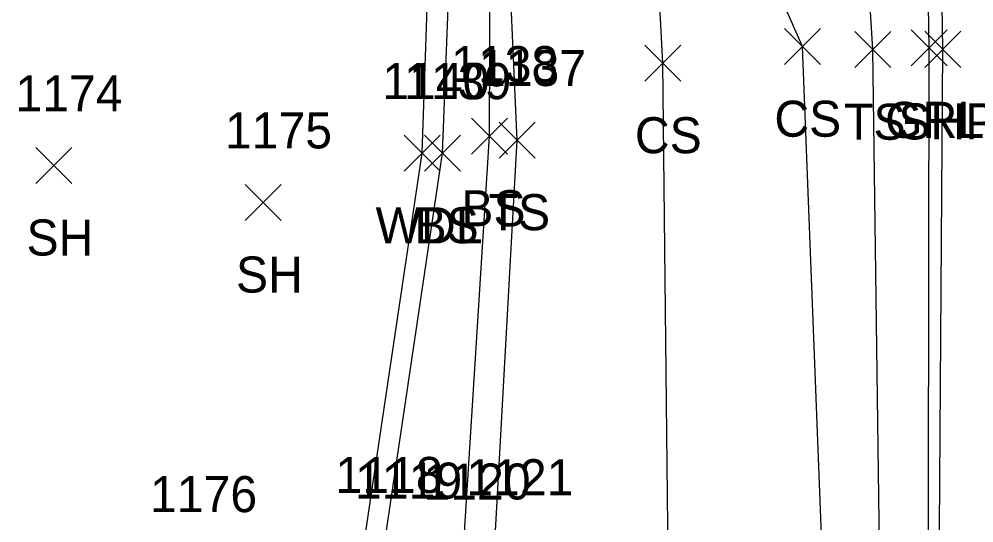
# Model space of a CAD drawing. Extents: x 1618262 to 1622220, y 273782 to 283685.
# Drawn here: x 1621993.1 to 1622046.2, y 282720.6 to 282748.6 of the extents above; entities that cross this region are included whole.
import ezdxf

# ---------------------------------------------------------------- set-up
doc = ezdxf.new("R2010")
doc.units = 0
for name, color, linetype in [('L_A', 7, 'Continuous'), ('L_I', 7, 'Continuous'), ('L_TIC', 7, 'Continuous'), ('LAWA', 7, 'Continuous'), ('LELB', 7, 'Continuous'), ('P_A', 7, 'Continuous'), ('P_TIC', 7, 'Continuous'), ('PSP', 7, 'Continuous'), ('R_A', 7, 'Continuous'), ('R_TIC', 7, 'Continuous'), ('RGR', 7, 'Continuous')]:
    doc.layers.add(name, color=color, linetype=linetype)

msp = doc.modelspace()

# ---------------------------------------------------------------- linework, layer by layer
at = {"layer": 'L_TIC'}
for points in [[(1622035.634, 282746.032), (1622037.634, 282748.032)], [(1622037.634, 282746.032), (1622035.634, 282748.032)], [(1622039.536, 282745.865), (1622041.536, 282747.865)], [(1622041.536, 282745.865), (1622039.536, 282747.865)], [(1622027.888, 282745.116), (1622029.888, 282747.116)], [(1622029.888, 282745.116), (1622027.888, 282747.116)], [(1622018.25, 282741.062), (1622020.25, 282743.062)], [(1622020.25, 282741.062), (1622018.25, 282743.062)], [(1622019.798, 282740.845), (1622021.798, 282742.845)], [(1622021.798, 282740.845), (1622019.798, 282742.845)], [(1622014.512, 282740.117), (1622016.512, 282742.117)], [(1622016.512, 282740.117), (1622014.512, 282742.117)], [(1622015.651, 282740.117), (1622017.651, 282742.117)], [(1622017.651, 282740.117), (1622015.651, 282742.117)], [(1621994.057, 282739.438), (1621996.057, 282741.438)], [(1621996.057, 282739.438), (1621994.057, 282741.438)], [(1622005.69, 282737.383), (1622007.69, 282739.383)], [(1622007.69, 282737.383), (1622005.69, 282739.383)]]:
    msp.add_lwpolyline(points, dxfattribs=at)
at = {"layer": 'LAWA'}
msp.add_lwpolyline([(1622012.261, 282719.262), (1622015.512, 282741.117), (1622016.402, 282766.923), (1622013.003, 282796.989), (1622009.949, 282826.463), (1622001.868, 282858.825)], dxfattribs=at)
at = {"layer": 'LELB'}
for points in [[(1622031.53, 282480.209), (1622034.92, 282519.516), (1622036.308, 282559.668), (1622038.549, 282600.481), (1622040.575, 282634.794), (1622041.384, 282671.626), (1622041.057, 282708.261), (1622040.536, 282746.865), (1622039.334, 282766.475), (1622038.366, 282807.145), (1622036.997, 282847.689), (1622035.465, 282881.364), (1622030.123, 282906.905), (1622032.201, 282930.97)], [(1622011.792, 282703.523), (1622017.803, 282718.897), (1622019.25, 282742.062), (1622019.347, 282767.736), (1622022.846, 282795.877), (1622021.207, 282825.793), (1622021.001, 282858.668), (1622021.577, 282889.835), (1622019.372, 282916.251), (1622019.074, 282930.132)], [(1622006.83, 282701.587), (1622009.972, 282709.565), (1622013.354, 282718.948), (1622016.651, 282741.117), (1622017.648, 282766.711), (1622013.003, 282796.989)], [(1622011.792, 282703.523), (1622019.526, 282719.135), (1622020.798, 282741.845), (1622019.651, 282767.692), (1622022.846, 282795.877)], [(1622038.036, 282634.62), (1622038.492, 282672.044), (1622038.146, 282708.503), (1622036.634, 282747.032), (1622027.782, 282767.08)], [(1622029.212, 282715.273), (1622028.888, 282746.116), (1622027.782, 282767.08)]]:
    msp.add_lwpolyline(points, dxfattribs=at)
at = {"layer": 'P_TIC'}
for points in [[(1622043.427, 282745.882), (1622045.427, 282747.882)], [(1622045.427, 282745.882), (1622043.427, 282747.882)]]:
    msp.add_lwpolyline(points, dxfattribs=at)
at = {"layer": 'PSP'}
msp.add_lwpolyline([(1622024.53, 282364.695), (1622029.224, 282410.341), (1622032.133, 282444.404), (1622034.721, 282480.169), (1622038.065, 282518.937), (1622040.189, 282559.981), (1622041.775, 282599.797), (1622043.576, 282635.077), (1622043.931, 282671.705), (1622044.179, 282709.624), (1622044.427, 282746.882), (1622044.138, 282766.852), (1622043.312, 282807.356), (1622042.106, 282847.846), (1622040.006, 282882.115), (1622036.278, 282931.352)], dxfattribs=at)
at = {"layer": 'R_TIC'}
for points in [[(1622042.681, 282745.97), (1622044.681, 282747.97)], [(1622044.681, 282745.97), (1622042.681, 282747.97)]]:
    msp.add_lwpolyline(points, dxfattribs=at)
at = {"layer": 'RGR'}
msp.add_lwpolyline([(1622023.476, 282364.894), (1622028.185, 282410.184), (1622031.232, 282444.188), (1622033.737, 282480.242), (1622036.802, 282518.899), (1622039.036, 282560.065), (1622040.978, 282599.772), (1622042.921, 282635.171), (1622043.063, 282671.763), (1622043.615, 282709.363), (1622043.681, 282746.97), (1622043.35, 282766.727), (1622042.763, 282807.193), (1622041.251, 282847.718), (1622039.436, 282882.181), (1622035.129, 282907.981)], dxfattribs=at)

# ---------------------------------------------------------------- texts
at = {"layer": 'L_A'}
for s, p in [('CS', (1622035.075, 282742.032)), ('TS', (1622038.945, 282741.865)), ('CS', (1622027.329, 282741.116)), ('BS', (1622017.691, 282737.062)), ('TS', (1622019.208, 282736.845)), ('WDL', (1622012.929, 282736.117)), ('BS', (1622015.092, 282736.117)), ('SH', (1621993.545, 282735.438)), ('SH', (1622005.178, 282733.383))]:
    msp.add_text(s, height=2, dxfattribs=at).set_placement(p)
at = {"layer": 'L_I'}
for s, p in [('1138', (1622017.125, 282745.062)), ('1137', (1622018.672, 282744.845)), ('1140', (1622013.3, 282744.117)), ('1139', (1622014.518, 282744.117)), ('1174', (1621992.931, 282743.438)), ('1175', (1622004.564, 282741.383)), ('1118', (1622010.703, 282722.262)), ('1118', (1622010.703, 282722.262)), ('1119', (1622011.788, 282721.948)), ('1121', (1622017.967, 282722.135)), ('1120', (1622015.591, 282721.897)), ('1176', (1622000.405, 282721.197))]:
    msp.add_text(s, height=2, dxfattribs=at).set_placement(p)
at = {"layer": 'P_A'}
msp.add_text('SHP', height=2, dxfattribs=at).set_placement((1622041.963, 282741.882))
at = {"layer": 'R_A'}
msp.add_text('GRL', height=2, dxfattribs=at).set_placement((1622041.224, 282741.97))

doc.saveas('drawing.dxf')
